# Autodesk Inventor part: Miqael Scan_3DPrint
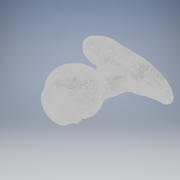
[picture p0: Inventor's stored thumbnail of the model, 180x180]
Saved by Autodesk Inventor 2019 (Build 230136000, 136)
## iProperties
Created: 2019-03
Part Number: Miqael Scan_3DPrint
Material: Generic
Document SubType Name: Modeling
Designer: aramy
Density: 1 g/cm^3
Appearance: Default
Author: aramy
Part Number: Miqael Scan
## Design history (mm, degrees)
node "Miqael Scan"
  node "MeshFeature1"
